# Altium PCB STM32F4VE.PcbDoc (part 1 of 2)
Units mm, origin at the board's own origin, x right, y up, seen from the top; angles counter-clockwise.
Board outline 98.7 x 95.5 mm, 2 copper layers (Top Layer, Bottom Layer); 103 components, 124 nets, 470 pads, 212 vias.
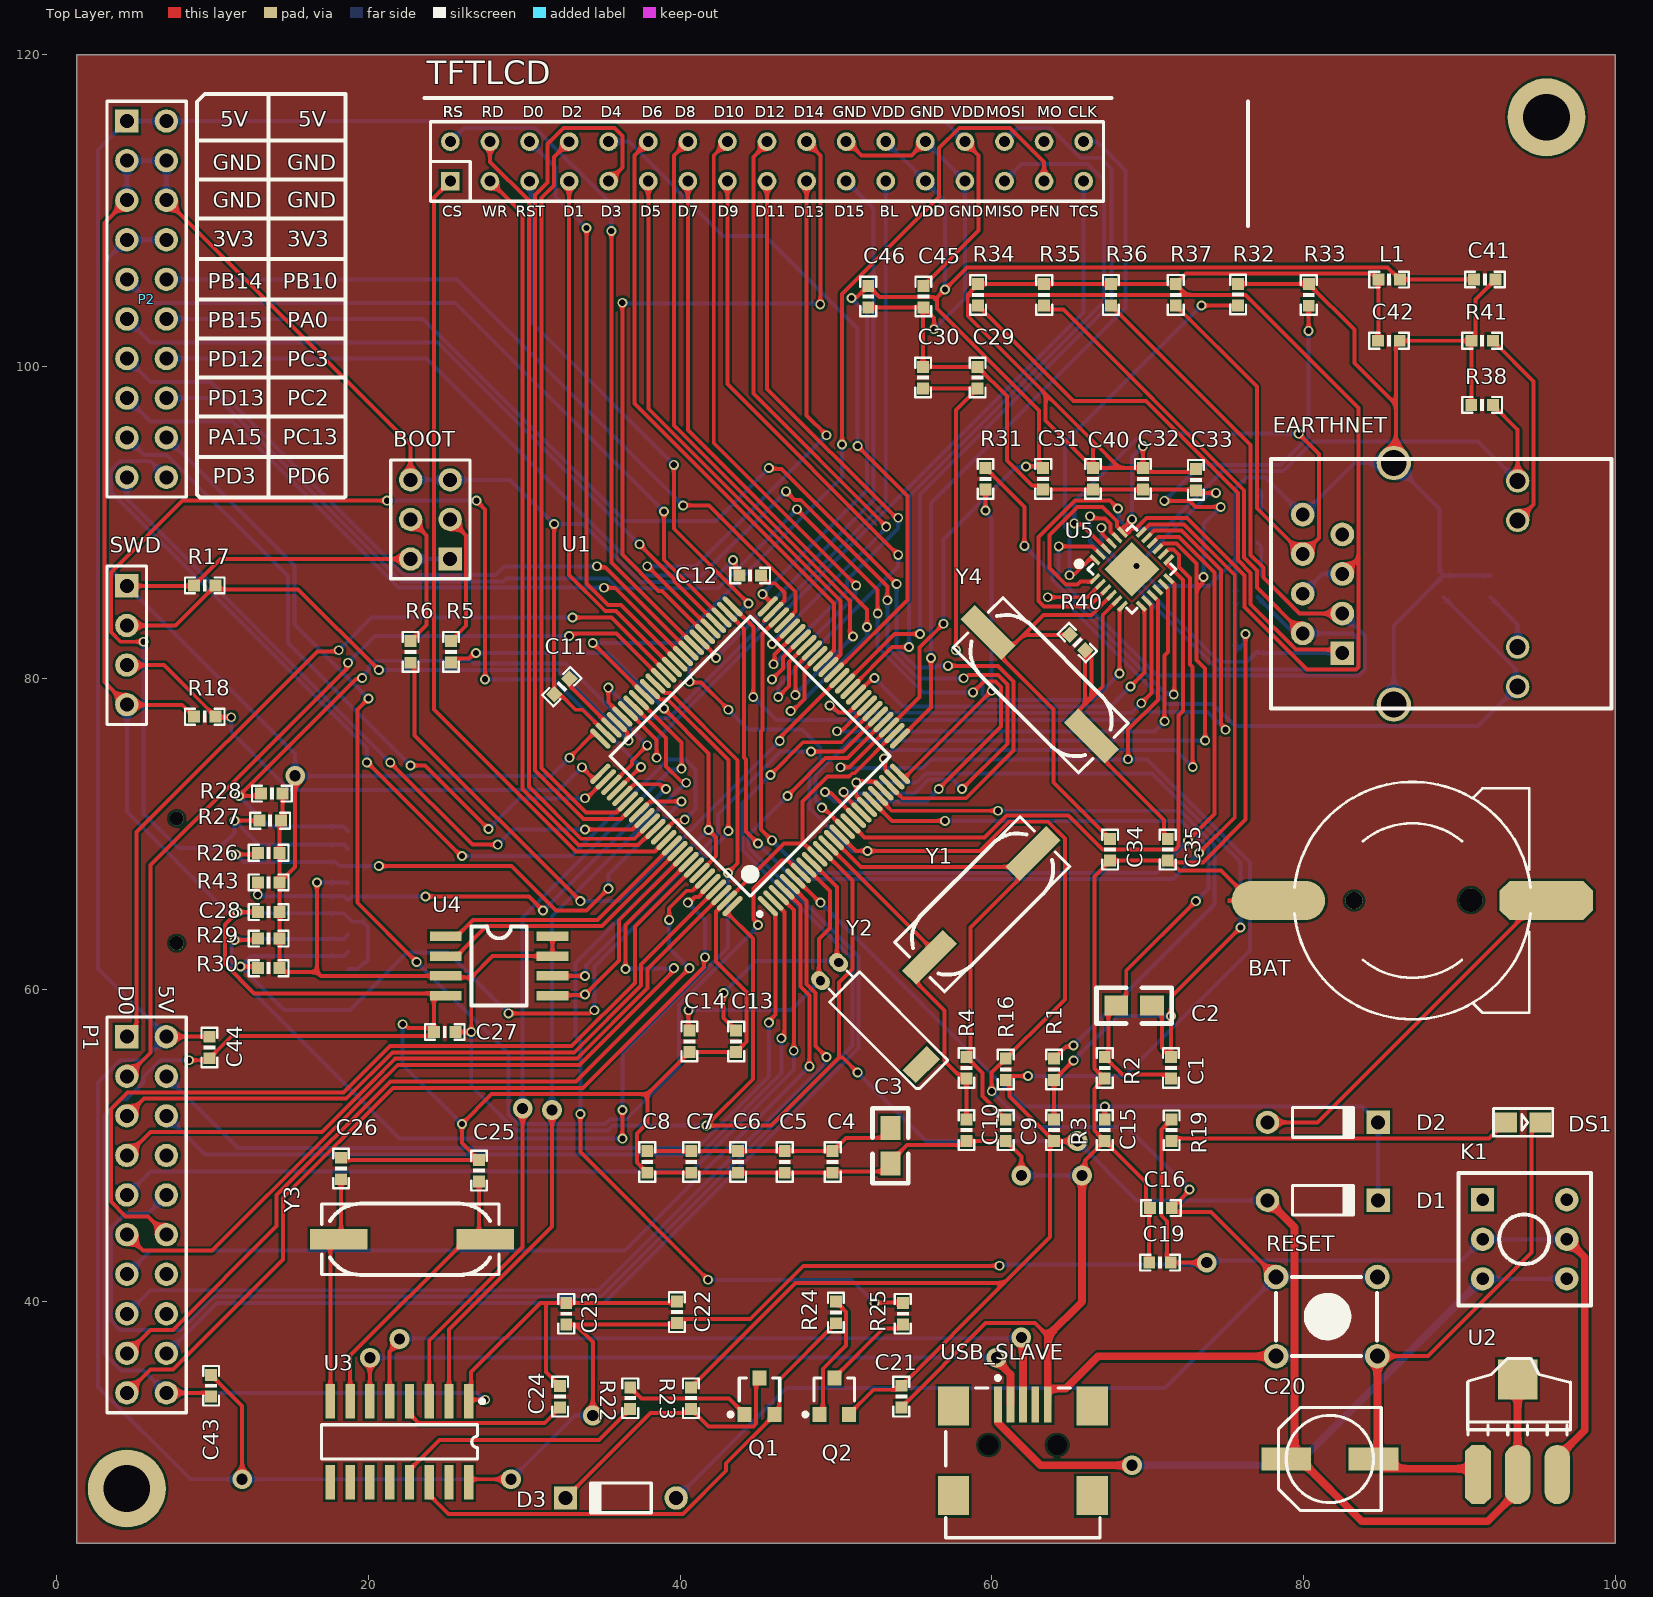
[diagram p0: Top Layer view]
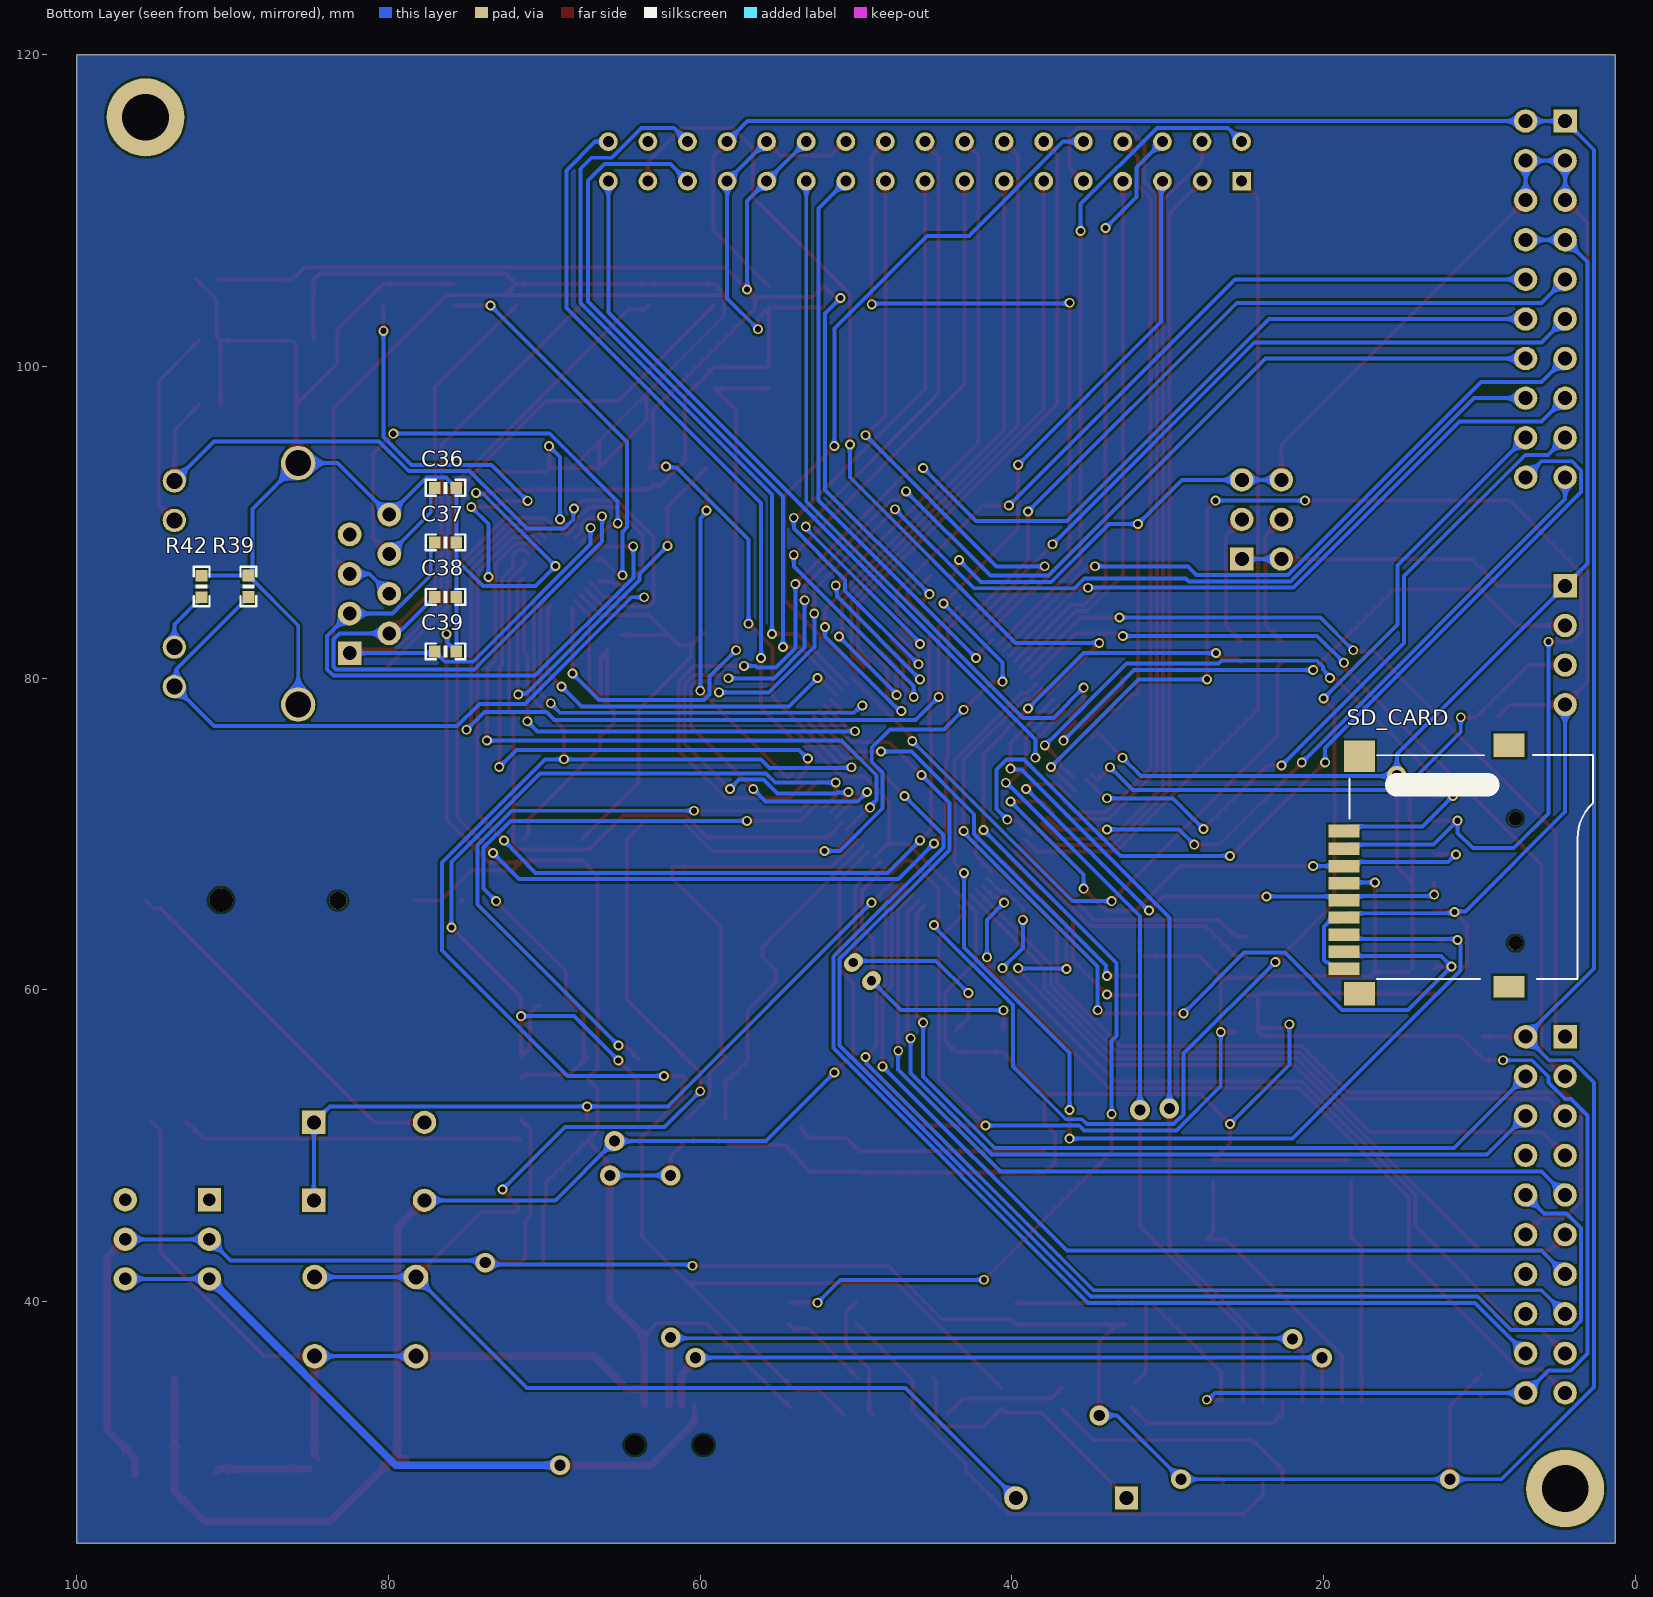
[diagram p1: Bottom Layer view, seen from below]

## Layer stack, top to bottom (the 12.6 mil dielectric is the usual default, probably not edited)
Top Solder: solder mask 0.0102, Solder Resist, Dk 3.5
Top Layer: signal copper 0.0356
Dielectric 1: dielectric 0.32, FR-4, Dk 4.8
Bottom Layer: signal copper 0.0356
Bottom Solder: solder mask 0.0102, Solder Resist, Dk 3.5

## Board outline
1.3,120 1.3,24.5 100,24.5 100,120

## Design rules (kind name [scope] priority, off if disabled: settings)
Clearance [All] p1: gap=0.152 ignorepadtopadclearanceinfootprint=TRUE
HoleSize [All] p1: absolutevalues=TRUE maxlimit=2.54 minlimit=0.2 maxpercent=80.000 minpercent=20.000
PolygonConnect [All] p1: connectstyle=Relief reliefconductorwidth=0.254 reliefentries=4 polygonreliefangle="90 Angle" airgapwidth=0.254
RoutingVias [All] p1: holewidth=0.4 width=0.635 viastyle="Through Hole" minholewidth=0.3 minwidth=0.5 maxholewidth=0.711 maxwidth=1.27
SolderMaskExpansion [All] p1: expansion=0.102
UnRoutedNet [All] p1: checkbadconnections=TRUE
Width [All] p1: maxlimit=0.7 minlimit=0.127 preferedwidth=0.254
28 further rules are at their usual default settings.

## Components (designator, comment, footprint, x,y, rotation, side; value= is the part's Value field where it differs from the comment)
BAT "BATT" BATM 87,65.737 r90 top
BOOT "Header 3X2" HDR2X3 25.247,87.656 r90 top
C1 "104" 0603P 71.5,55 r90 top
C2 "106" 0805 68,59 r0 top
C3 "106" 0805 53.5,48.858 r90 top
C4 "104" 0603P 49.792,48.958 r90 top
C5 "104" 0603P 46.721,48.958 r90 top
C6 "104" 0603P 43.721,48.958 r90 top
C7 "104" 0603P 40.721,48.958 r90 top
C8 "104" 0603P 37.893,48.958 r90 top
C9 "22P" 0603P 60.902,51 r270 top
C10 "22P" 0603P 58.383,51 r270 top
C11 "106" 0603P 32.409,79.466 r45 top
C12 "106" 0603P 44.5,86.6 r0 top
C13 "12P" 0603P 43.6,56.7 r90 top
C14 "12P" 0603P 40.6,56.7 r90 top
C15 "104" 0603P 67.251,51 r90 top
C16 "104" 0603P 70.855,46 r0 top
C19 "104" 0603P 70.807,42.5 r180 top
C20 "220uF" CC6.56.5 81.7,29.9 r0 top
C21 "104" 0603P 54.2,33.9 r90 top
C22 "104" 0603P 39.8,39.32 r270 top
C23 "10UF" 0603P 32.7,39.22 r90 top
C24 "104" 0603P 32.3,33.9 r270 top
C25 "22P" 0603P 27.1,48.4 r270 top
C26 "22P" 0603P 18.244,48.547 r270 top
C27 "104" 0603P 24.9,57.3 r180 top
C28 "104" 0603P 13.6,65 r0 top
C29 "104" 0603P 59.097,99.3 r270 top
C30 "10UF" 0603P 55.598,99.3 r270 top
C31 "104" 0603P 63.3,92.8 r90 top
C32 "104" 0603P 69.702,92.8 r90 top
C33 "104" 0603P 73.1,92.736 r90 top
C34 "22P" 0603P 67.6,69 r270 top
C35 "22P" 0603P 71.3,69 r270 top
C36 "10" 0603P 76.346,92.222 r0 bottom
C37 "10" 0603P 76.346,88.722 r0 bottom
C38 "10" 0603P 76.346,85.222 r0 bottom
C39 "10" 0603P 76.346,81.722 r0 bottom
C40 "223" 0603P 66.5,92.8 r90 top
C41 "104" 0603P 91.649,105.591 r180 top
C42 "10UF" 0603P 85.5,101.663 r180 top
C43 "104" 0603P 9.9,34.6 r90 top
C44 "104" 0603P 9.798,56.301 r90 top
C45 "104" 0603P 55.617,104.5 r270 top
C46 "104" 0603P 52.081,104.5 r270 top
D1 "Diode 1N4148" DO-35 81.251,46.498 r0 top
D2 "Diode 1N4148" DO-35 81.251,51.5 r0 top
D3 "Diode 1N4148" DO-35 36.2,27.4 r180 top
DS1 "LED1" SMDLED 93,51.5 r0 top
EARTHNET "RJ45" HR911105A 88.85,86.066 r270 top
K1 "BUTTON" BTN8.5*8.5 91.5,46.54 r0 top
L1 "220R,2.0A,0.05DCR" 0603P 85.5,105.591 r0 top
P1 "Header 10X2" HDR2X10 4.5,57 r270 top
P2 "Header 10X2" HDR2X10 4.5,115.76 r270 top
Q1 "S8050" SOT-23R 45.1,33.8 r0 top
Q2 "S8550" SOT-23R 49.9,33.8 r0 top
R1 "0R" 0603P 64,54.9 r90 top
R2 "0R" 0603P 67.251,55 r90 top
R3 "0R" 0603P 64,51 r90 top
R4 "1M" 0603P 58.382,55 r90 top
R5 "10K" 0603P 25.3,81.7 r90 top
R6 "10K" 0603P 22.707,81.7 r270 top
R16 "10K" 0603P 60.9,54.9 r90 top
R17 "10K" 0603P 9.5,85.964 r0 top
R18 "10K" 0603P 9.5,77.541 r0 top
R19 "2k" 0603P 71.545,50.998 r90 top
R22 "1K" 0603P 36.8,33.8 r90 top
R23 "10K" 0603P 40.7,33.8 r90 top
R24 "1K" 0603P 50,39.3 r90 top
R25 "1K" 0603P 54.3,39.22 r270 top
R26 "10K" 0603P 13.6,68.8 r0 top
R27 "10K" 0603P 13.7,70.865 r0 top
R28 "10K" 0603P 13.8,72.6 r0 top
R29 "10K" 0603P 13.6,63.3 r0 top
R30 "10K" 0603P 13.6,61.4 r0 top
R31 "510R" 0603P 59.6,92.8 r90 top
R32 "12K" 0603P 75.811,104.621 r270 top
R33 "10K" 0603P 80.351,104.607 r270 top
R34 "49.9R" 0603P 59.123,104.607 r90 top
R35 "49.9R" 0603P 63.365,104.607 r90 top
R36 "49.9R" 0603P 67.65,104.609 r90 top
R37 "49.9R" 0603P 71.809,104.609 r90 top
R38 "10K" 0603P 91.476,97.54 r180 top
R39 "10K" 0603P 89,85.898 r90 bottom
R40 "1M" 0603P 65.5,82.3 r315 top
R41 "510R" 0603P 91.476,101.663 r0 top
R42 "510R" 0603P 92,85.898 r270 bottom
R43 "10K" 0603P 13.6,66.9 r0 top
RESET "KEY_M" KEY_M 78.251,41.58 r0 top
SD_CARD "Component_1" TF_SD 18.7,70.2 r270 bottom
SWD "Header 4" HDR1X4 4.5,85.93 r270 top
TFTLCD "TFT_LCD" TFT_LCD 385,-185.5 r0 top
U1 "STM32F4VE" LQFP100 44.5,75 r135 top
U2 "AMS1117-3.3" AMS1117 91.209,28.906 r0 top
U3 "CH340G" SOP16M 22,31 r180 top
U4 "W25Q128" SOIC-8 24.956,63.442 r0 top
U5 "LAN8720A" QFN24 69,87 r45 top
USB_SLAVE "USB-B(Mini)" USB/SM0.8-6H5 62,25.55 r270 top
Y1 "8MHz" 49S_SMD 56,62.1 r45 top
Y2 "32.768KHz" JZ32768 50.174,61.76 r225 top
Y3 "12MHz" 49S_SMD 27.5,44 r180 top
Y4 "25MHz" 49S_SMD 59.755,82.945 r315 top

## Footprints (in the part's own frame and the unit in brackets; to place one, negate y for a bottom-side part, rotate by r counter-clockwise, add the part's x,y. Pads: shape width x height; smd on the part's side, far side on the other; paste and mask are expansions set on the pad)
49S_SMD [mil]
  rect 146x51 smd: 1(0,0) 2(370,0)
  silkscreen extent -35,-90 413,90
0603P [mil]
  rect 30x30 smd: 1(-27,0) 2(27.5,-0.07)
  silkscreen extent -50,-20 50,20
0805 [mil]
  rect 60x50 smd: 1(0,-0.06) 2(90,-0.06)
  silkscreen extent -50,-45 140,45
AMS1117 [mil]
  oct 65x150 smd: 1(0.03,-0.06)
  oval 65x150 smd: 2(100.03,-0.06) 3(200.03,-0.06)
  rect 100x100 smd: 4(100.03,239.94)
  silkscreen extent -26,100 234,293
BATM [mm]
  round 1.1 hole 1.1 unplated: 0(0,3.748)
  round 1.5 hole 1.5 unplated: 0(0.025,-3.752)
  oct 2.5x6 smd: 1(0,-8.602)
  oval 2.5x6 smd: 2(0,8.598)
  silkscreen extent -7.62,-7.58 7.62,7.57
BTN8.5*8.5 [mm]
  rect 1.5x1.5 hole 0.8: 1(0,0)
  round 1.5 hole 0.8: 2(0,-2.54) 3(0,-5.08) 4(5.4,-5.08) 5(5.4,-2.54) 6(5.4,0)
  silkscreen extent -1.55,-6.79 6.95,1.71
CC6.56.5 [mm]
  rect 3.2x1.5 smd: 1(-2.794,0) 2(2.8,0)
  silkscreen extent -3.3,-3.3 3.3,3.3
DO-35 [mm] "Diode, Axial; Body 3.8 x 1.9 mm (LxDia. max), Lead Dia. 0.53 mm (max)"
  round 1.5 hole 0.9: 1(-3.55,0)
  rect 1.5x1.5 hole 0.9: 2(3.55,0)
  silkscreen extent -1.95,-0.95 2.05,0.95
HDR1X4 [mm]
  rect 1.5x1.5 hole 0.9: 1(0,0)
  round 1.5 hole 0.9: 2(2.54,0) 3(5.08,0) 4(7.62,0)
  silkscreen extent -1.27,-1.27 8.89,1.27
HDR2X3 [mm]
  rect 1.5x1.5 hole 0.9: 1(0,0)
  round 1.5 hole 0.9: 2(0,2.54) 3(2.54,0) 4(2.54,2.54) 5(5.08,0) 6(5.08,2.54)
  silkscreen extent -1.27,-1.27 6.35,3.81
HDR2X10 [mm] "Connector; Header; 10x2 Position"
  rect 1.5x1.5 hole 0.9: 1(0,0)
  round 1.5 hole 0.9: 2(0,2.54) 3(2.54,0) 4(2.54,2.54) 5(5.08,0) 6(5.08,2.54) 7(7.62,0) 8(7.62,2.54) 9(10.16,0) 10(10.16,2.54) 11(12.7,0) 12(12.7,2.54) 13(15.24,0) 14(15.24,2.54) 15(17.78,0) 16(17.78,2.54) 17(20.32,0) 18(20.32,2.54) 19(22.86,0) 20(22.86,2.54)
  silkscreen extent -1.27,-1.27 24.13,3.81
HR911105A [mil]
  rect 60x60 hole 35: 1(175.2,-250)
  round 60 hole 35: 2(125.2,-350) 3(75.2,-250) 4(25.2,-350) 5(-24.8,-250) 6(-74.8,-350) 7(-124.8,-250) 8(-174.8,-350)
  round 59.06 hole 40.16: 9(259.84,192.91) 12(-259.84,192.91)
  round 59.05 hole 40.16: 10(160,192.91) 11(-160,192.91)
  round 86.61 hole 64.96: 13(305.12,-120) 14(-305.12,-120)
  silkscreen extent -315,-430 315,430
JZ32768 [mm]
  oval 1x1.3 hole 0.6: 1(0,0) 2(1.64,0)
  rect 2.2x1.2 smd: 3(0.875,8.382)
  silkscreen extent -0.53,0.76 2.2,9.4
KEY_M [mil]
  round 62 hole 38: 1(0,0) 1(255.91,0) 2(0,-200) 2(255.91,-200)
  silkscreen extent 0,-200 255,0
LQFP100 [mm] "LQFP, 100-Leads, Body 16.2x16.2mm (max), Pitch 0.50mm, IPC Medium Density"
  oval 1.7x0.33 smd: 1(-7.6,6) 2(-7.6,5.5) 3(-7.6,5) 4(-7.6,4.5) 5(-7.6,4) 6(-7.6,3.5) 7(-7.6,3) 8(-7.6,2.5) 9(-7.6,2) 10(-7.6,1.5) 11(-7.6,1) 12(-7.6,0.5) 13(-7.6,0) 14(-7.6,-0.5) 15(-7.6,-1) 16(-7.6,-1.5) 17(-7.6,-2) 18(-7.6,-2.5) 19(-7.6,-3) 20(-7.6,-3.5) 21(-7.6,-4) 22(-7.6,-4.5) 23(-7.6,-5) 24(-7.6,-5.5) 25(-7.6,-6) 51(7.6,-6) 52(7.6,-5.5) 53(7.6,-5) 54(7.6,-4.5) 55(7.6,-4) 56(7.6,-3.5) 57(7.6,-3) 58(7.6,-2.5) 59(7.6,-2) 60(7.6,-1.5) 61(7.6,-1) 62(7.6,-0.5) 63(7.6,0) 64(7.6,0.5) 65(7.6,1) 66(7.6,1.5) 67(7.6,2) 68(7.6,2.5) 69(7.6,3) 70(7.6,3.5) 71(7.6,4) 72(7.6,4.5) 73(7.6,5) 74(7.6,5.5) 75(7.6,6)
  oval 0.33x1.7 smd: 26(-6,-7.6) 27(-5.5,-7.6) 28(-5,-7.6) 29(-4.5,-7.6) 30(-4,-7.6) 31(-3.5,-7.6) 32(-3,-7.6) 33(-2.5,-7.6) 34(-2,-7.6) 35(-1.5,-7.6) 36(-1,-7.6) 37(-0.5,-7.6) 38(0,-7.6) 39(0.5,-7.6) 40(1,-7.6) 41(1.5,-7.6) 42(2,-7.6) 43(2.5,-7.6) 44(3,-7.6) 45(3.5,-7.6) 46(4,-7.6) 47(4.5,-7.6) 48(5,-7.6) 49(5.5,-7.6) 50(6,-7.6) 76(6,7.6) 77(5.5,7.6) 78(5,7.6) 79(4.5,7.6) 80(4,7.6) 81(3.5,7.6) 82(3,7.6) 83(2.5,7.6) 84(2,7.6) 85(1.5,7.6) 86(1,7.6) 87(0.5,7.6) 88(0,7.6) 89(-0.5,7.6) 90(-1,7.6) 91(-1.5,7.6) 92(-2,7.6) 93(-2.5,7.6) 94(-3,7.6) 95(-3.5,7.6) 96(-4,7.6) 97(-4.5,7.6) 98(-5,7.6) 99(-5.5,7.6) 100(-6,7.6)
  silkscreen extent -7.72,-6.35 6.35,6.85, body extent -7.05,-7.05 7.05,7.05, height 1.6
QFN24 [mm]
  rect 0.8x0.25 smd: 1(-2.101,1.25) 2(-2.101,0.75) 3(-2.101,0.25) 4(-2.101,-0.25) 5(-2.101,-0.75) 6(-2.101,-1.25) 13(2.101,-1.25) 14(2.101,-0.75) 15(2.101,-0.25) 16(2.101,0.25) 17(2.101,0.75) 18(2.101,1.25)
  rect 0.25x0.8 smd: 7(-1.25,-2.101) 8(-0.75,-2.101) 9(-0.25,-2.101) 10(0.25,-2.101) 11(0.75,-2.101) 12(1.25,-2.101) 19(1.25,2.101) 20(0.75,2.101) 21(0.25,2.101) 22(-0.25,2.101) 23(-0.75,2.101) 24(-1.25,2.101)
  rect 2.5x2.5 smd: 25(0,0)
  silkscreen extent -2.31,-2 2,2.79
SMDLED [mm]
  rect 1.4x1.27 smd: 1(0.001,-0.002) 2(2.211,-0.002)
  silkscreen extent -0.8,-0.89 3.01,0.89
SOIC-8 [mil]
  rect 80x24 smd: 1(0,0) 2(0,-50.06) 3(0,-100.06) 4(0,-150.06) 5(270,-150) 6(270,-100) 7(270,-50) 8(270,0)
  silkscreen extent 65,-175 205,25
SOP16M [mm]
  rect 0.6x2.2 smd: 1(-4.445,-2.6) 2(-3.175,-2.6) 3(-1.905,-2.6) 4(-0.635,-2.6) 5(0.635,-2.6) 6(1.905,-2.6) 7(3.175,-2.6) 8(4.445,-2.6) 9(4.445,2.6) 10(3.175,2.6) 11(1.905,2.6) 12(0.635,2.6) 13(-0.635,2.6) 14(-1.905,2.6) 15(-3.175,2.6) 16(-4.445,2.6)
  silkscreen extent -5.42,-2.72 5,1.1
SOT-23R [mm]
  rect 0.9x0.95 smd: 1(0.95,-1.048) 2(-0.95,-1.048) 3(0,1.302)
  silkscreen extent -1.98,-1.17 1.3,1.3
TF_SD [mm]
  round 0.9 hole 0.9 unplated: 0(-0.8,11) 0(7.2,11)
  rect 0.85x2 smd: 1(0,0)
  rect 0.8x2 smd: 2(1.15,0) 3(2.25,0) 4(3.35,0) 5(4.45,0) 6(5.55,0) 7(6.65,0) 8(7.75,0) 9(8.85,0)
  rect 1.5x2 smd: 10(-5.5,10.6) 10(10.45,1)
  rect 2x2 smd: 10(-4.8,1)
  rect 1.4x2 smd: 10(10,10.6)
  silkscreen extent -4.87,0.36 9.49,16
TFT_LCD [mm]
  rect 1.2x1.2 hole 0.7: 1(-359.738,297.401)
  round 1.2 hole 0.7: 2(-359.738,299.941) 3(-357.198,297.401) 4(-357.198,299.941) 5(-354.656,297.395) 6(-354.658,299.941) 7(-352.116,297.395) 8(-352.116,299.935) 9(-349.578,297.401) 10(-349.578,299.941) 11(-347.038,297.401) 12(-347.038,299.941) 13(-344.498,297.401) 14(-344.498,299.941) 15(-341.958,297.401) 16(-341.958,299.941) 17(-339.418,297.401) 18(-339.418,299.941) 19(-336.878,297.401) 20(-336.878,299.941) 21(-334.338,297.401) 22(-334.338,299.941) 23(-331.798,297.401) 24(-331.798,299.941) 25(-329.258,297.401) 26(-329.258,299.941) 27(-326.718,297.401) 28(-326.718,299.941) 29(-324.178,297.401) 30(-324.178,299.941) 31(-321.638,297.401) 32(-321.638,299.941) 33(-319.098,297.401) 34(-319.098,299.941)
  silkscreen extent -361.39,294.51 -308.54,302.73
USB/SM0.8-6H5 [mm]
  rect 2.3x0.5 smd: 1(-7.85,-1.6) 2(-7.85,-0.8) 3(-7.85,0) 4(-7.85,0.8) 5(-7.85,1.6)
  rect 2.5x2 smd: 6(-7.75,4.45) 7(-1.996,4.45) 8(-7.75,-4.45) 9(-1.996,-4.45)
  round 0.6 hole 1.27 unplated: MH1(-5.25,2.2) MH2(-5.25,-2.2)
  silkscreen extent -9.67,-4.95 0.7,4.95

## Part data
BAT: library part BAT
BOOT: "Header, 3-Pin, Dual row"
C1 C2 C3 C4 C5 C6 C7 C8 C9 C10 C11 C12 C13 C14 C15 C16 C19 C21 C22 C23 C24 C25 C26 C27 C28 C29 C30 C31 C32 C33 C34 C35 C36 C37 C38 C39 C40 C41 C42 C43 C44 C45 C46: library part C
C20: library part CAP
D1 D2 D3: "High Conductance Fast Diode"
DS1: library part LED2, "Typical RED, GREEN, YELLOW, AMBER GaAs LED", PackageDocument=Feb-2002
EARTHNET: library part HR911105
L1: library part L
P1 P2: "Header, 10-Pin, Dual row"
Q1: library part NPN, "8050/BCW846/BCW847"
Q2: library part PNP, "8550/BCW68"
R1 R2 R3 R4 R5 R6 R16 R17 R18 R19 R22 R23 R24 R25 R26 R27 R28 R29 R30 R31 R32 R33 R34 R35 R36 R37 R38 R39 R40 R41 R42 R43: library part R
SWD: "Header, 4-Pin"
U2: library part AMS1117
U3: "USB2UART"
U4: library part W25X16, "W25X16;SST25VF016;MX25L1605"
U5: library part LAN8720, "ETH PHY"
USB_SLAVE: library part USB5
Y1 Y2 Y3 Y4: library part XTAL, "Crystal Oscillator"

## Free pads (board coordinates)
  round 5 hole 3: 1(95.602,116) 2(4.5,28)

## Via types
v1: diameter 0.635, hole 0.4, Top Layer to Bottom Layer, 197 vias
v2: diameter 1.27, hole 0.711, Top Layer to Bottom Layer, 15 vias

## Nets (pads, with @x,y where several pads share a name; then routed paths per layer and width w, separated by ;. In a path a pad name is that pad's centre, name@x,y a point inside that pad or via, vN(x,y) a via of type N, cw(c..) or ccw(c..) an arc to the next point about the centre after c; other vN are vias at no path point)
3V3: BOOT.1 BOOT.2 C20.1 C21.2 C27.1 C28.2 C31.2 C41.2 C46.1 D1.1 L1.2 P2.7 P2.8 Q2.1 R3.1 R16.1 R17.1 R23.2 R26.2 R27.2 R28.2 R29.2 R30.2 R43.2 SD_CARD.4 SWD.1 TFTLCD.24 TFTLCD.25 U1.11 U1.28 U1.50 U1.75 U1.100 U2.2 U2.4 U4.3 U4.7 U4.8 U5.9 | length 504.2
  Top Layer w0.254: SWD.1@4.5,85.93 8.78,85.93 R17.1@8.814,85.964 10.506,87.656 BOOT.2@22.707,87.656 ; R28.2@14.499,72.598 14.499,70.964 R27.2@14.399,70.864 14.299,70.764 R26.2@14.299,68.798 R43.2@14.299,66.898 ; v2(15.3,73.745) 15.3,67.9 R43.2@14.299,66.898 ; v1(16.7,66.898) 16.7,61.144 ; C27.1@25.586,57.3 25.587,57.302 v1(26.6,57.302) 26.6,60.8 ; U4.8@31.814,63.442 U4.7@31.814,62.172 27.972,62.172 26.6,60.8 ; v1(32.9,74.9) 34.482,76.482 34.532,76.482 U1.75@34.883,76.131 ; R23.2@40.702,34.498 47.403,41.2 60.803,41.2 ; U1.100@43.369,65.383 42.999,65.014 42.999,64.964 44.668,63.295 44.668,54.268 v1(41.7,51.3) 45.844,51.3 50.2,55.656 ; v1(45.3,85.4) 45.832,84.868 45.832,84.818 U1.50@45.631,84.617 ; U1.11@49.167,68.919 51.06,67.026 51.06,61.331 50.2,60.471 50.2,55.656 ; v1(50.3,74.295) 50.866,74.295 U1.28@53.41,76.838 55.368,78.797 55.368,81.968 v1(56.9,83.5) ; Q2.1@50.85,32.752 50.85,32.777 52.417,34.345 53.948,34.345 C21.2@54.202,34.599 60.803,41.2 ; v1(51,104.4) 51.073,104.473 51.368,104.473 C46.1@52.081,105.186 52.805,104.462 56.225,104.462 56.387,104.3 56.5,104.3 56.5,103.74 63.048,97.192 C31.2@63.048,93.752 ; v1(51.4,54.697) 50.441,55.656 50.2,55.656 ; 56.112,104.47 56.271,104.47 56.391,104.35 v1(57,104.959) 58.415,106.374 85.414,106.374 L1.2@86.199,105.589 90.947,105.589 C41.2@90.951,105.593 ; v1(62.2,93.6) 63.048,93.6 C31.2@63.048,93.752 ; v1(62.332,54.483) 62.317,54.468 61.154,54.468 R16.1@60.9,54.214 61.154,53.96 61.154,53.16 R3.1@64,50.314 ; C31.2@63.302,93.498 C31.2@63.048,93.752 ; v2(65.5,50.3) 64.014,50.3 R3.1@64,50.314 ; v1(68.753,74.802) 68.753,76.709 70.659,78.615 70.659,84.985 70.309,85.335 U5.9@70.309,85.337 ; R43.2@14.299,66.898 C28.2@14.299,64.998 R29.2@14.299,63.298 R30.2@14.299,61.398 14.553,61.144 16.7,61.144 ; 16.7,61.144 16.944,60.9 24.245,60.9 24.345,60.8 26.6,60.8 ; 60.803,41.2 63.746,44.143 63.746,50.06 R3.1@64,50.314
  Top Layer w0.5: D1.1@77.701,46.498 79.44,44.759 79.44,30.216 C20.1@79.756,29.9 ; C20.1@78.906,29.9 C20.1@79.756,29.9 ; U2.4@93.75,35 U2.2@93.75,28.904 93.75,27.824 91.826,25.9 83.756,25.9 C20.1@79.756,29.9
  Bottom Layer w0.254: P2.8@7.04,108.14 P2.7@4.5,108.14 3.064,106.704 3.064,87.366 SWD.1@4.5,85.93 15.3,75.13 15.3,74.19 15.769,73.721 31.721,73.721 v1(32.9,74.9) ; v1(16.7,66.898) 18.652,66.898 SD_CARD.4@18.7,66.85 ; BOOT.2@22.707,87.656 BOOT.1@25.247,87.656 ; v1(26.6,57.302) 26.6,53.832 29.453,50.979 35.365,50.979 35.682,51.297 41.697,51.297 v1(41.7,51.3) ; v1(45.3,85.4) 51.997,92.097 51.997,103.403 v1(51,104.4) ; v1(50.3,74.295) 50.345,74.25 55.556,74.25 56.109,74.802 v1(68.753,74.802) 69.955,74.802 76.568,68.189 76.568,62.541 68.51,54.483 v1(62.332,54.483) ; v1(51.4,54.697) 55.797,50.3 v2(65.5,50.3) 69.302,46.498 D1.1@77.701,46.498 ; TFTLCD.24@53.202,114.441 TFTLCD.25@55.742,111.901 57,110.642 v1(57,104.959) ; v1(56.9,83.5) 56.9,88.912 61.515,93.527 62.127,93.527 v1(62.2,93.6)
3V3_E: C32.2 C33.2 C40.2 C42.2 EARTHNET.4 EARTHNET.5 L1.1 R34.2 R35.2 R36.2 R37.2 U5.1 U5.19 | length 155
  Top Layer w0.254: 58.488,104.597 76.292,104.597 83.541,97.348 83.541,87.737 ; R35.2@63.367,105.306 67.651,105.306 67.653,105.307 R37.2@71.811,105.307 ; U5.1@66.436,86.206 65.689,86.206 65.5,86.018 64.753,86.018 63.703,87.067 63.703,89.191 65.508,90.997 67.122,90.997 68.04,90.079 68.04,89.731 U5.19@68.206,89.564 ; R36.2@67.651,105.307 59.126,105.307 58.462,104.643 58.462,103.251 63.454,98.259 ; U5.19@68.285,89.485 v1(69,90.2) ; U5.19@68.398,89.37 68.59,89.178 68.593,89.178 69.018,89.603 69.261,89.603 69.942,90.284 72.521,90.284 76.213,86.593 76.213,84.585 80.224,80.574 83.378,80.574 83.541,80.738 83.541,87.737 ; v1(69.703,94.897) C32.2@69.703,93.498 ; 72.535,104.583 R37.2@71.811,105.307 ; C33.2@73.102,93.434 72.912,93.244 69.957,93.244 C32.2@69.703,93.498 ; EARTHNET.5@82.5,86.696 83.541,87.737 ; C42.2@84.802,101.665 84.814,101.677 L1.1@84.814,105.591 84.438,105.968 72.471,105.968 R37.2@71.811,105.307 ; 63.454,98.259 66.502,95.212 ; 63.454,98.259 63.454,96.546 C40.2@66.502,93.499 ; C40.2@66.502,93.499 66.502,95.212 ; C40.2@66.502,93.499 68.215,93.498 ; 66.502,95.212 68.215,93.498 ; 68.215,93.498 C32.2@69.703,93.498
  Bottom Layer w0.254: v1(69,90.2) 69,94.193 v1(69.703,94.897) ; EARTHNET.4@79.96,85.426 81.23,86.696 EARTHNET.5@82.5,86.696
5V: C19.1 C22.2 C23.1 C43.2 C44.2 C45.1 K1.2 K1.5 P1.2 P2.1 P2.2 R19.2 TFTLCD.28 U2.3 U3.16 | length 302
  Top Layer w0.254: P1.2@7.04,57 C44.2@9.8,57 ; C43.2@9.902,35.299 11.9,33.3 v2(11.9,28.6) ; U3.16@26.445,28.4 26.445,28.427 26.618,28.6 v2(29.152,28.6) ; C23.1@32.7,38.534 33.266,38.534 ; v2(34.4,32.697) 34.4,37.4 33.266,38.534 ; C45.1@55.617,105.186 59.161,108.73 59.161,113.562 TFTLCD.28@58.282,114.441 ; v1(60.5,42.3) 47.928,42.3 44.504,38.876 40.052,38.876 39.711,38.534 33.266,38.534 ; R19.2@71.546,51.697 70.884,51.035 70.884,45.511 71.239,45.156 71.239,42.754 C19.1@71.493,42.5 v2(73.8,42.5)
  Top Layer w0.5: U2.3@96.29,28.904 96.29,29.983 98.052,31.746 98.052,42.848 K1.5@96.9,44
  Bottom Layer w0.254: P2.2@7.04,115.76 P2.1@4.5,115.76 2.658,113.918 2.658,61.382 P1.2@7.04,57 5.529,55.489 4.074,55.489 2.658,54.074 2.658,34.526 8.584,28.6 v2(29.152,28.6) 33.249,32.697 v2(34.4,32.697) ; P2.2@7.06,115.76 56.962,115.76 TFTLCD.28@58.282,114.441 ; v1(60.5,42.3) 60.573,42.373 73.673,42.373 73.947,42.647 90.147,42.647 K1.2@91.5,44 K1.5@96.9,44
BOOT0: R5.1 R25.1 U1.94 | length 76.8
  Top Layer w0.254: R5.1@25.3,81.014 25.554,81.268 26.45,81.268 26.797,81.616 v1(26.9,81.616) ; v1(33.6,52.038) 33.6,49.602 v1(41.8,41.402) ; v1(38.964,78.054) 41.834,75.184 41.834,70.28 v1@41.823,70.269 ; U1.94@41.247,67.505 41.247,67.525 42.308,68.586 42.308,69.795 v1(41.834,70.269) ; v1(52.476,39.929) 54.277,39.929 R25.1@54.3,39.906
  Bottom Layer w0.254: v1(26.9,81.616) 35.402,81.616 v1(38.964,78.054) ; v1(33.6,52.038) 33.6,56.738 33.301,57.037 33.301,61.737 v1(41.834,70.269) ; v1(41.8,41.402) 51.004,41.402 v1(52.476,39.929)
BOOT1: R6.2 U1.37 | length 42.5
  Top Layer w0.254: R6.2@22.705,81.002 22.959,80.748 22.959,76.341 v1(33.6,65.7) ; v1(46.4,75.969) 46.473,76.042 46.473,76.266 U1.37@50.228,80.02
  Bottom Layer w0.254: v1(33.6,65.7) 36.131,65.7 v1(46.4,75.969)
D+: U3.5 USB_SLAVE.3 | length 48.5
  Top Layer w0.254: U3.5@21.365,33.6 21.365,36.798 22,37.433 v2(22,37.6) ; v2(61.9,37.7) v2@62,37.6
  Top Layer w0.5: USB_SLAVE.3@62,33.4 v2@62,37.6
  Bottom Layer w0.254: v2(22,37.6) 22.05,37.65 61.85,37.65 v2(61.9,37.7)
D-: U3.6 USB_SLAVE.2 | length 46.4
  Top Layer w0.254: U3.6@20.095,33.6 20.097,33.602 20.097,36.397 v2(20.1,36.4)
  Top Layer w0.5: v2(60.3,36.4) 60.3,36.241 61.2,35.341 USB_SLAVE.2@61.2,33.4
  Bottom Layer w0.254: v2(20.1,36.4) v2(60.3,36.4)
DCMI_D0: P1.1 U1.63 | length 54.6
  Top Layer w0.254: P1.1@4.5,57 5.123,57.623 5.123,70.123 16.733,81.733 18.033,81.733 v1(18.1,81.8) ; v1(33.1,83.9) 35.6,83.9 U1.63@39.126,80.374
  Bottom Layer w0.254: v1(18.1,81.8) 20.2,83.9 v1(33.1,83.9)
DCMI_D1: P1.3 U1.64 | length 54.4
  Top Layer w0.254: P1.3@4.5,54.46 6.011,55.971 6.011,68.011 18.7,80.7 v1(18.7,81) ; v1(32.884,82.71) 32.987,82.71 33.141,82.864 35.928,82.864 U1.64@38.772,80.02
  Bottom Layer w0.254: v1(18.7,81) 20.41,82.71 v1(32.884,82.71)
DCMI_D2: P1.5 U1.97 | length 44.6
  Top Layer w0.254: P1.5@4.5,51.92 5.604,53.024 18.579,53.024 21.548,55.993 33.212,55.993 37.503,60.284 37.503,61.639 U1.97@42.308,66.444
DCMI_D3: P1.7 U1.98 | length 45.8
  Top Layer w0.254: P1.7@4.5,49.38 6.011,50.891 17.02,50.891 20.187,54.057 21.717,55.587 33.38,55.587 37.91,60.116 37.91,61.339 U1.98@42.661,66.09
DCMI_D4: P1.9 U1.3 | length 57.7
  Top Layer w0.254: U1.3@46.338,66.09 47.3,65.129 v1(47.3,56.1)
  Bottom Layer w0.254: P1.9@4.5,46.84 6.011,48.351 40.744,48.351 47.3,54.906 v1(47.3,56.1)
DCMI_D5: P1.11 U1.92 | length 54.8
  Top Layer w0.254: P1.11@4.5,44.3 5.529,43.271 9.975,43.271 17.189,50.484 20.594,53.889 21.885,55.18 33.549,55.18 39.527,61.159 39.527,61.325 v1(39.6,61.398) ; v1(36.5,61.35) 36.5,64.172 U1.92@40.54,68.212
  Bottom Layer w0.254: v1(36.5,61.35) 36.524,61.374 39.576,61.374 v1(39.6,61.398)
DCMI_D6: P1.13 U1.4 | length 61.3
  Top Layer w0.254: U1.4@46.692,66.444 47.723,65.413 47.723,60.215 48.3,59.638 v1(48.3,55.1)
  Bottom Layer w0.254: P1.13@4.5,41.76 6.011,43.271 36.471,43.271 v1(48.3,55.1)
DCMI_D7: P1.15 U1.5 | length 64
  Top Layer w0.254: U1.5@47.046,66.798 48.129,65.714 48.129,60.383 48.706,59.806 48.706,56.394 v1(49.4,55.7)
  Bottom Layer w0.254: P1.15@4.5,39.22 6.011,40.731 34.775,40.731 49.327,55.283 49.327,55.627 v1(49.4,55.7)
DCMI_HR: P1.18 U1.29 | length 80.8
  Top Layer w0.254: v1(46.9,72.454) 49.337,74.892 50.756,74.892 U1.29@53.056,77.192
  Bottom Layer w0.254: P1.18@7.04,36.68 10.278,39.918 35.111,39.918 51.466,56.272 51.466,62.145 47.962,65.649 47.907,65.649 44.403,69.153 44.403,69.958 v1(46.9,72.454)
DCMI_PCLK: P1.10 U1.31 | length 95.1
  Top Layer w0.254: v1(45.8,73.8) 47.897,75.897 50.347,75.897 U1.31@52.349,77.899
  Bottom Layer w0.254: P1.10@7.04,46.84 5.864,45.664 4.408,45.664 3.471,44.726 3.471,38.794 4.074,38.191 7.976,38.191 10.11,40.324 34.943,40.324 51.06,56.441 51.06,61.976 47.794,65.242 47.739,65.242 43.997,68.984 43.997,71.997 v1(45.8,73.8)
DCMI_VS: P1.12 U1.93 | length 56.3
  Top Layer w0.254: P1.12@7.04,44.3 5.864,45.476 4.408,45.476 3.471,46.414 3.471,52.346 4.555,53.431 18.411,53.431 21.38,56.4 33.044,56.4 37.097,60.453 37.097,64.061 U1.93@40.894,67.858
ETH_MDC: U1.16 U5.13 | length 42
  Top Layer w0.254: U1.16@50.935,70.687 50.955,70.687 51.847,69.795 59.539,69.795 60.944,71.2 64.928,71.2 67.103,69.025 71.797,69.025 71.996,69.225 71.996,77.627 72.277,77.907 72.277,86.309 71.178,87.407 71.178,87.41 U5.13@71.37,87.602
ETH_MDIO: R31.1 U1.25 | length 21.4
  Top Layer w0.254: U1.25@54.117,73.869 54.368,73.618 54.418,73.618 v1(60,79.2) ; v1(59.6,90.768) R31.1@59.6,92.114
  Bottom Layer w0.254: v1(59.6,90.768) 59.6,90.665 60,90.265 v1(60,79.2)
ETH_RESET: R33.2 U1.15 U5.15 | length 74.1
  Top Layer w0.254: v1(49.1,71.7) 49.194,71.7 50.56,70.333 U1.15@50.581,70.333 ; U5.15@70.663,88.309 70.665,88.309 71.015,88.659 71.848,88.659 73.141,87.366 73.141,85.7 ; v1(71.08,91.389) 72.695,91.389 73.085,91 v1(74.7,91) ; v1(73.6,86.507) 73.527,86.434 73.527,86.086 73.141,85.7 ; v1(73.7,76) 73.7,80.622 73.141,81.181 73.141,85.7 ; v1(80.337,102.3) 80.337,103.655 80.349,103.667 R33.2@80.349,103.909
  Bottom Layer w0.254: v1(49.1,71.7) 49.1,71.803 48.703,72.2 48.703,73.777 50.926,76 v1(73.7,76) ; v1(71.08,91.389) 73.388,93.697 78.541,93.697 80.337,95.492 v1(80.337,102.3) ; v1(73.6,86.507) 73.6,89.9 v1(74.7,91)
F_CS: U1.89 U4.1 | length 16.9
  Top Layer w0.254: U4.1@24.956,63.442 25.667,63.442 26.722,64.496 34.704,64.496 U1.89@39.48,69.272
FSMC_A16: TFTLCD.2 U1.58 | length 43.2
  Top Layer w0.254: v1(35.59,108.7) 35.59,87.445 U1.58@40.894,82.142
  Bottom Layer w0.254: TFTLCD.2@25.262,114.441 26.141,115.32 30.706,115.32 35.59,110.436 v1(35.59,108.7)
FSMC_D0: TFTLCD.6 U1.61 | length 37.8
  Top Layer w0.254: v1(34,108.9) 34,86.083 35.37,84.713 36.201,84.713 U1.61@39.833,81.081
  Bottom Layer w0.254: TFTLCD.6@30.342,114.441 32.004,112.778 32.004,110.896 v1(34,108.9)
FSMC_D1: TFTLCD.7 U1.62 | length 34.3
  Top Layer w0.254: TFTLCD.7@32.884,111.895 32.884,86.624 35.201,84.306 35.901,84.306 U1.62@39.48,80.728
FSMC_D2: TFTLCD.8 U1.81 | length 47.9
  Top Layer w0.254: TFTLCD.8@32.884,114.435 31.904,113.456 31.904,111.637 31.106,110.839 31.106,74.25 33.956,71.4 35.93,71.4 36.63,72.101 U1.81@36.651,72.101
FSMC_D3: TFTLCD.9 U1.82 | length 57.2
  Top Layer w0.254: TFTLCD.9@35.422,111.901 36.301,112.78 36.301,114.805 35.786,115.32 32.525,115.32 31.498,114.293 31.498,111.806 30.699,111.007 30.699,74.082 33.81,70.971 36.208,70.971 36.984,71.747 U1.82@37.005,71.747
FSMC_D4: TFTLCD.10 U1.38 | length 46.3
  Top Layer w0.254: U1.38@49.874,80.374 50.181,80.681 50.23,80.681 50.235,80.676 54.597,85.038 54.597,91.703 v1(51.4,94.9)
  Bottom Layer w0.254: TFTLCD.10@35.422,114.441 36.718,114.441 42.77,108.388 45.456,108.388 51.4,102.444 v1(51.4,94.9)
FSMC_D5: TFTLCD.11 U1.39 | length 36.6
  Top Layer w0.254: TFTLCD.11@37.962,111.901 37.962,97.316 50.3,84.978 50.3,81.528 49.52,80.748 U1.39@49.52,80.728
FSMC_D6: TFTLCD.12 U1.40 | length 39.3
  Top Layer w0.254: TFTLCD.12@37.962,114.441 37.082,113.562 37.082,97.621 49.894,84.809 49.894,81.828 49.167,81.102 U1.40@49.167,81.081
FSMC_D7: TFTLCD.13 U1.41 | length 45.2
  Top Layer w0.254: TFTLCD.13@40.502,111.901 40.502,95.926 50.712,85.715 52,84.427 v1(52,83.285) ; v1(47.1,77.907) 47.173,77.98 47.295,77.98 47.997,78.682 47.997,80.598 48.813,81.414 U1.41@48.813,81.435
  Bottom Layer w0.254: v1(47.1,77.907) 47.203,77.907 47.628,78.332 47.647,78.332 52,82.685 v1(52,83.285)
FSMC_D8: TFTLCD.14 U1.42 | length 45.5
  Top Layer w0.254: TFTLCD.14@40.502,114.441 39.622,113.562 39.622,96.23 40.095,95.757 50.555,85.297 50.9,84.952 v1@50.9,82.6 ; v1(47.4,78.929) 47.413,78.942 47.413,80.741 U1.42@48.46,81.788
  Bottom Layer w0.254: v1(47.4,78.929) 47.4,78.985 v1(51.1,82.685)
FSMC_D9: TFTLCD.15 U1.43 | length 44.9
  Top Layer w0.254: TFTLCD.15@43.042,111.901 43.042,98.882 v1(54,87.924) ; v1(46.3,78.797) 47.006,79.503 47.006,81.042 U1.43@48.106,82.142
  Bottom Layer w0.254: v1(46.3,78.797) 46.308,78.804 46.308,79.495 54,87.188 v1(54,87.924)
FSMC_D10: TFTLCD.16 U1.44 | length 44.2
  Top Layer w0.254: TFTLCD.16@43.042,114.441 42.162,113.562 42.162,95.109 v1(51.309,85.962) ; v1(45.902,79.934) 46.6,80.632 46.6,81.343 U1.44@47.753,82.495
  Bottom Layer w0.254: v1(45.902,79.934) 51.236,85.268 51.236,85.889 v1(51.309,85.962)
FSMC_D11: TFTLCD.17 U1.45 | length 40.4
  Top Layer w0.254: TFTLCD.17@45.582,111.901 45.582,98.574 53.783,90.373 53.927,90.373 v1(54,90.3) ; v1(46,80.9) 46.073,80.973 46.073,81.521 47.399,82.848 U1.45@47.399,82.849
  Bottom Layer w0.254: v1(46,80.9) 50.712,85.612 50.712,86.312 54,89.6 v1(54,90.3)
FSMC_D12: TFTLCD.18 U1.46 | length 40.7
  Top Layer w0.254: TFTLCD.18@45.582,114.441 45.582,114.329 44.702,113.45 44.702,98.263 v1(53.234,89.731) ; v1(45.902,82.195) 45.975,82.268 46.111,82.268 U1.46@47.046,83.202
  Bottom Layer w0.254: v1(45.902,82.195) 45.902,82.297 53.234,89.629 v1(53.234,89.731)
FSMC_D13: TFTLCD.19 U1.55 | length 37.5
  Top Layer w0.254: v1(37.893,87.188) 37.949,87.188 41.934,83.202 U1.55@41.954,83.202 ; TFTLCD.19@48.122,111.901 48.122,96.878 v1(49.4,95.6)
  Bottom Layer w0.254: v1(37.893,87.188) 40.988,87.188 v1(49.4,95.6)
FSMC_D14: TFTLCD.20 U1.56 | length 47.1
  Top Layer w0.254: v1(36.298,104.1) 36.298,87.939 38.629,85.607 38.843,85.607 U1.56@41.601,82.849 ; TFTLCD.20@48.122,114.441 49.001,113.562 v1@49.001,104.001 ; v1(49,104) v1@49.001,104.001
  Bottom Layer w0.254: v1(36.298,104.1) 36.348,104.05 48.95,104.05 v1(49,104)
FSMC_D15: TFTLCD.21 U1.57 | length 37.1
  Top Layer w0.254: U1.57@41.247,82.495 42.227,81.516 42.227,81.373 v1(42.3,81.3)
  Bottom Layer w0.254: v1(42.3,81.3) 52.403,91.403 52.403,110.159 TFTLCD.21@50.662,111.901
FSMC_NE1: TFTLCD.1 U1.88 | length 53.3
  Top Layer w0.254: TFTLCD.1@25.262,111.901 24.218,110.857 24.218,77.989 33.316,68.89 38.37,68.89 39.105,69.626 U1.88@39.126,69.626
FSMC_NOE: TFTLCD.4 U1.85 | length 52
  Top Layer w0.254: TFTLCD.4@27.802,114.441 27.802,113.145 30.293,110.653 30.293,73.063 33.653,69.703 37.082,69.703 U1.85@38.065,70.687
FSMC_NWE: TFTLCD.3 U1.86 | length 50.2
  Top Layer w0.254: TFTLCD.3@27.802,111.901 29.887,109.816 29.887,72.894 33.484,69.297 37.304,69.297 38.195,70.188 U1.86@38.352,70.188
